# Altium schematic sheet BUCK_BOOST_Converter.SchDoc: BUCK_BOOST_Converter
size A3; Date: Not used; ApprovedBy: Not used; CheckedBy: Not used; Author: Not used; CompanyName: STMicroelectronics; DrawnBy: Not used; Engineer: Not used; Organization: Not used; Address1: Not used; Address2: Not used; Address3: Not used; Address4: Not used; DocumentNumber: Not used; Revision: Not used; SheetNumber: 7; SheetTotal: 12
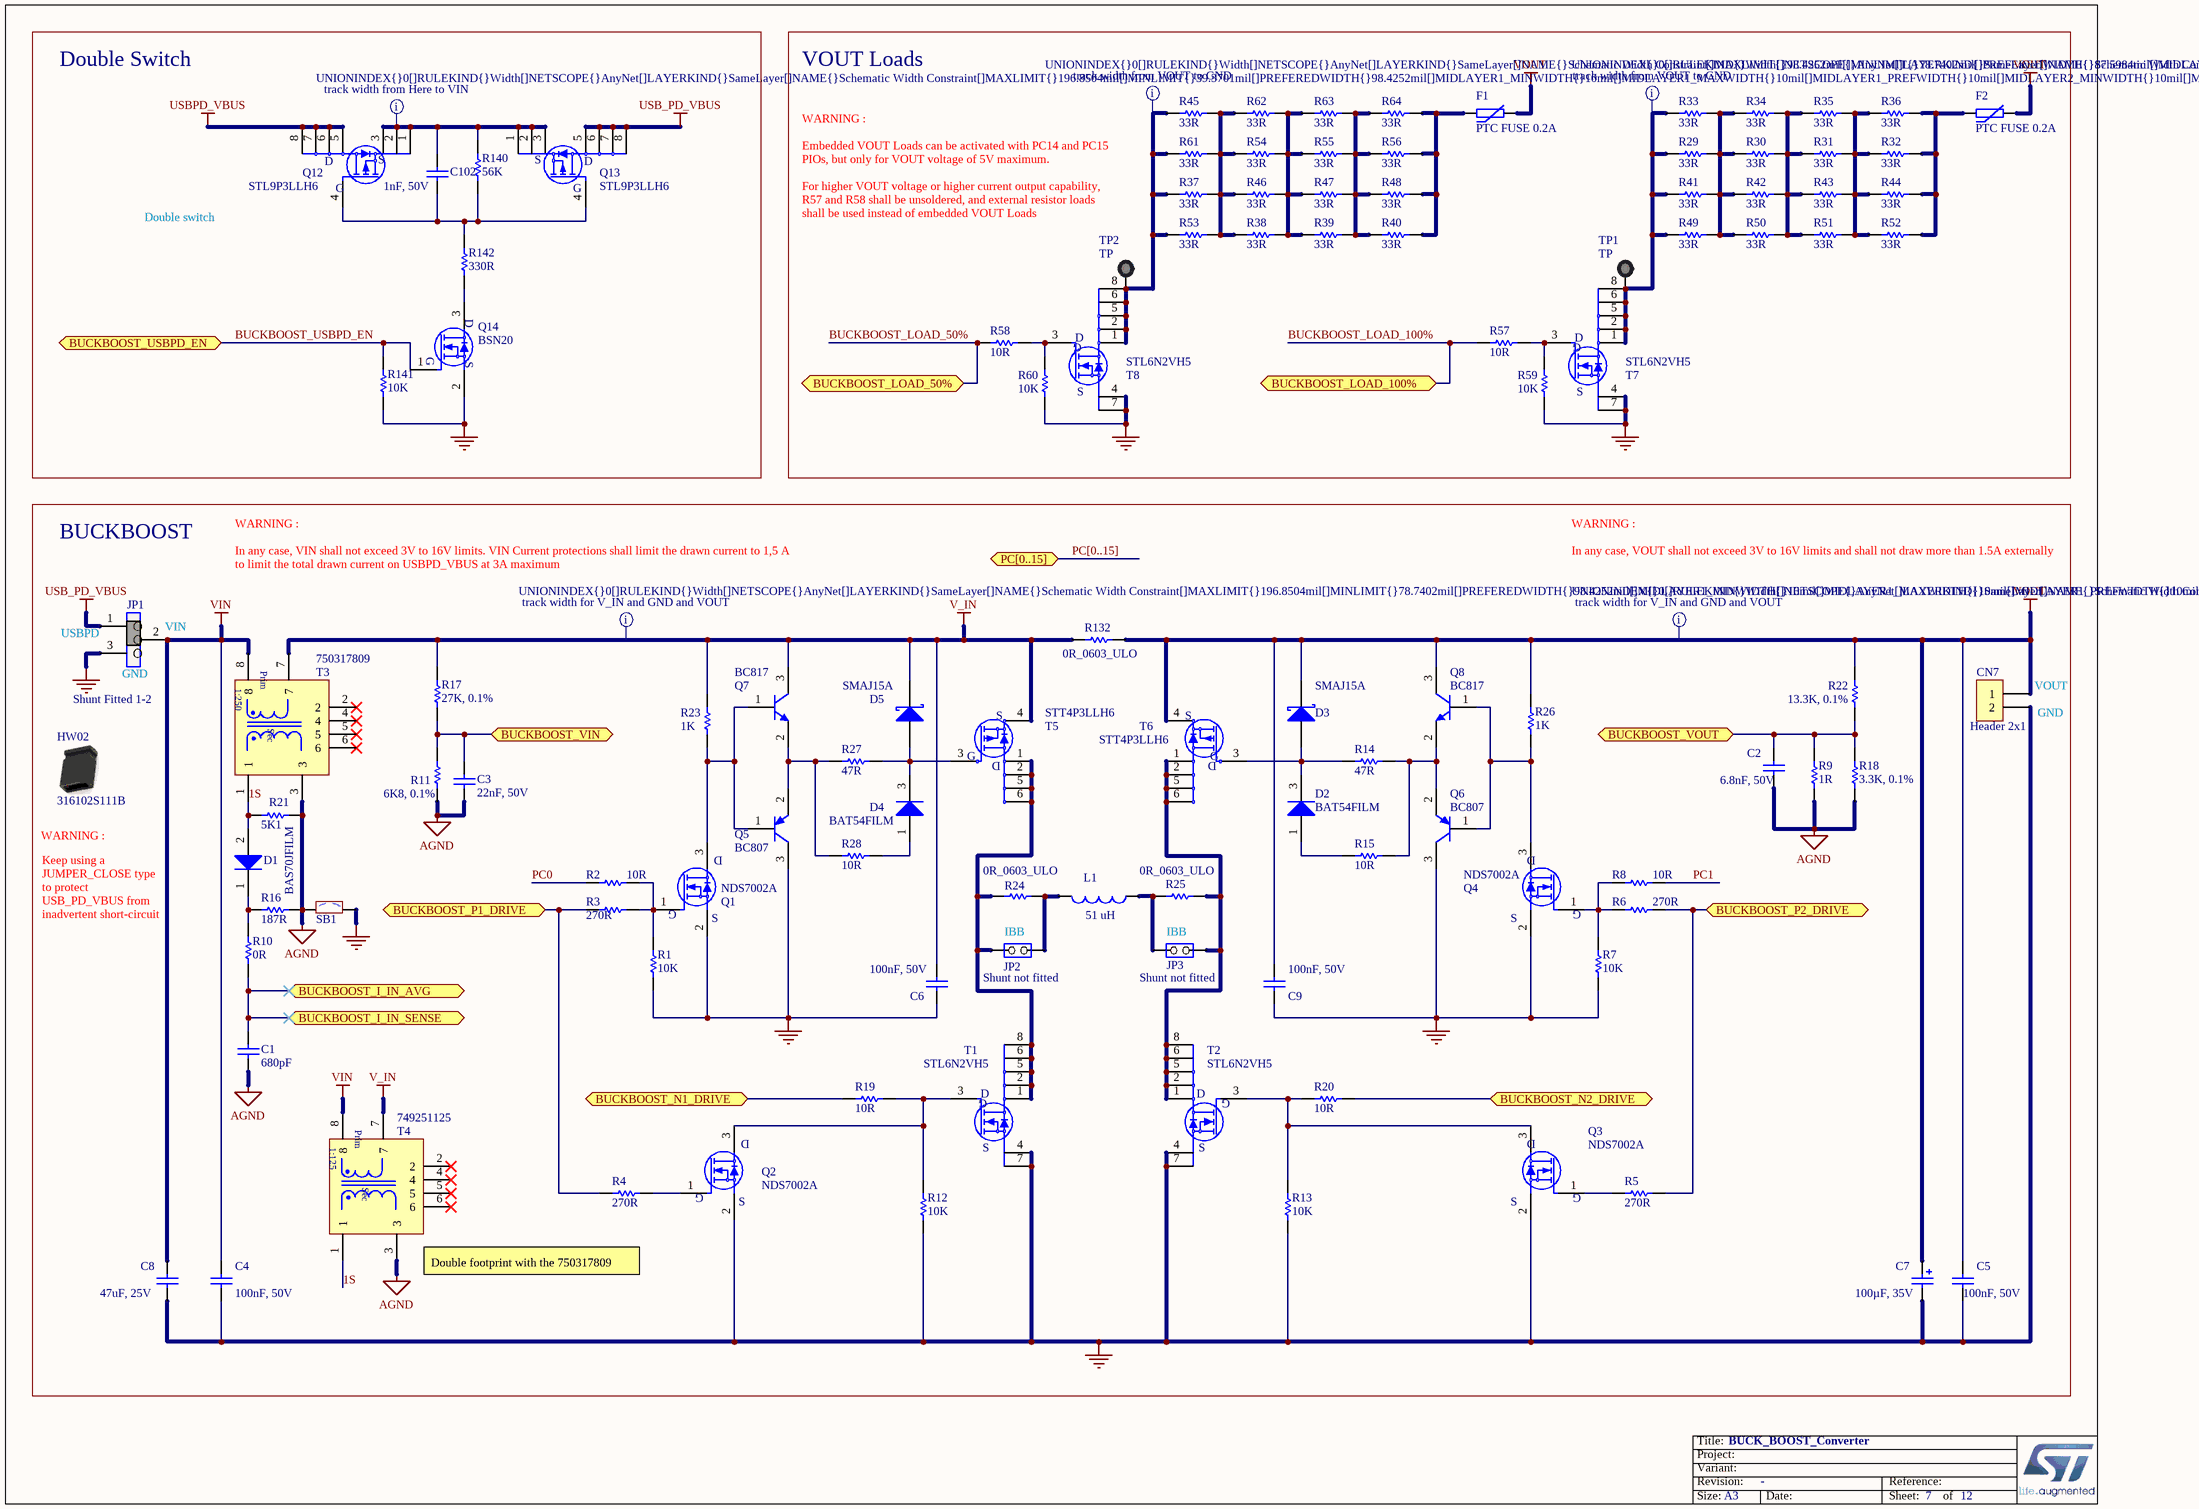
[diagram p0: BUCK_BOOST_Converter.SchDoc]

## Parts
C1  value 680pF  [C0603_H0P8]
C2  value 6.8nF, 50V  [C0603_H0P8]
C3  value 22nF, 50V  [C0603]
C4  value 100nF, 50V  [C0805_H0P85]
C5  value 100nF, 50V  [C0805_H0P85]
C6  value 100nF, 50V  [C0805_H0P85]
C7  value 100µF, 35V  [CPOL_WURTH_WCAP-ASLL_8X10P5]
C8  value 47uF, 25V  [C1206_H1P6]  (hidden comment: Capacitor)
C9  value 100nF, 50V  [C0805_H0P85]
C102  value 1nF, 50V  [C0805_H0P6]
CN7  Header 2x1  [CON_LYCONN_313102S141346]
D1  value BAS70JFILM  [DIO_SOD323_1K_2A]  (hidden comment: DIODE_1K_2A)
D2  value BAT54FILM  [DIO_SOT23_SC59_1A_2NC_3K_H1P4]
D3  value SMAJ15A  [DIO_SMA_1A_2K]
D4  value BAT54FILM  [DIO_SOT23_SC59_1A_2NC_3K_H1P4]
D5  value SMAJ15A  [DIO_SMA_1A_2K]
F1  value PTC FUSE 0.2A  [PTC_EATON_FUSE_PTS1812_H0P9]
F2  value PTC FUSE 0.2A  [PTC_EATON_FUSE_PTS1812_H0P9]
HW02  value 316102S111B  (hidden comment: JUMPER_CLOSE)
JP1  value Shunt Fitted 1-2  [CON_SAMTEC_TSW-103-07-F-S]  (hidden comment: Jumper_Header 3x1 Fitted 1-2)
JP2  value Shunt not fitted  [CON_988-JIUBABA_313102S111116]  (hidden comment: Jumper_Header 2x1)
JP3  value Shunt not fitted  [CON_988-JIUBABA_313102S111116]  (hidden comment: Jumper_Header 2x1)
L1  value 51 uH  [IND_SUNLORD_SWPA5040S]  (hidden comment: Inductor)
Q1  value NDS7002A  [ICC_SOT23-3L_H1P12]
Q2  value NDS7002A  [ICC_SOT23-3L_H1P12]
Q3  value NDS7002A  [ICC_SOT23-3L_H1P12]
Q4  value NDS7002A  [ICC_SOT23-3L_H1P12]
Q5  value BC807  [ICC_SOT23-3L_H1P12]
Q6  value BC807  [ICC_SOT23-3L_H1P12]
Q7  value BC817  [NPN_SOT23]
Q8  value BC817  [NPN_SOT23]
Q12  value STL9P3LLH6  [MOS_POWERFLAT_3P3X3P3_P065]
Q13  value STL9P3LLH6  [MOS_POWERFLAT_3P3X3P3_P065]
Q14  value BSN20  [MOS_SOT23]
R1  value 10K  [R0805]
R2  value 10R  [R0805_H0P5]
R3  value 270R  [R0805_H0P5]
R4  value 270R  [R0805_H0P5]
R5  value 270R  [R0805_H0P5]
R6  value 270R  [R0805_H0P5]
R7  value 10K  [R0805]
R8  value 10R  [R0805_H0P5]
R9  value 1R  [R1206_H0P55]
R10  value 0R  [R0603]  (hidden comment: Resistor)
R11  value 6K8, 0.1%  [R0805]
R12  value 10K  [R0805]
R13  value 10K  [R0805]
R14  value 47R  [R0805_H0P5]
R15  value 10R  [R0805_H0P5]
R16  value 187R  [R1206_H0P55]  (hidden comment: Resistor)
R17  value 27K, 0.1%  [R0805]
R18  value 3.3K, 0.1%  [R0805]
R19  value 10R  [R0805_H0P5]
R20  value 10R  [R0805_H0P5]
R21  value 5K1  [R0603]  (hidden comment: Resistor)
R22  value 13.3K, 0.1%  [R0805]
R23  value 1K  [R0603]
R24  value 0R_0603_ULO  [R0603]
R25  value 0R_0603_ULO  [R0603]
R26  value 1K  [R0603]
R27  value 47R  [R0805_H0P5]
R28  value 10R  [R0805_H0P5]
R29  value 33R  [R1206_H0P55]
R30  value 33R  [R1206_H0P55]
R31  value 33R  [R1206_H0P55]
R32  value 33R  [R1206_H0P55]
R33  value 33R  [R1206_H0P55]
R34  value 33R  [R1206_H0P55]
R35  value 33R  [R1206_H0P55]
R36  value 33R  [R1206_H0P55]
R37  value 33R  [R1206_H0P55]
R38  value 33R  [R1206_H0P55]
R39  value 33R  [R1206_H0P55]
R40  value 33R  [R1206_H0P55]
R41  value 33R  [R1206_H0P55]
R42  value 33R  [R1206_H0P55]
R43  value 33R  [R1206_H0P55]
R44  value 33R  [R1206_H0P55]
R45  value 33R  [R1206_H0P55]
R46  value 33R  [R1206_H0P55]
R47  value 33R  [R1206_H0P55]
R48  value 33R  [R1206_H0P55]
R49  value 33R  [R1206_H0P55]
R50  value 33R  [R1206_H0P55]
R51  value 33R  [R1206_H0P55]
R52  value 33R  [R1206_H0P55]
R53  value 33R  [R1206_H0P55]
R54  value 33R  [R1206_H0P55]
R55  value 33R  [R1206_H0P55]
R56  value 33R  [R1206_H0P55]
R57  value 10R  [R0805_H0P5]
R58  value 10R  [R0805_H0P5]
R59  value 10K  [R0603]
R60  value 10K  [R0603]
R61  value 33R  [R1206_H0P55]
R62  value 33R  [R1206_H0P55]
R63  value 33R  [R1206_H0P55]
R64  value 33R  [R1206_H0P55]
R132  value 0R_0603_ULO  [R0603]
R140  value 56K  [R0603]
R141  value 10K  [R0603]
R142  value 330R  [R0603]
SB1  (no value)  [SOLDER-BRIDGE_R0603-0R]
T1  value STL6N2VH5  [MOS_POWERFLAT_2X2_P065]
T2  value STL6N2VH5  [MOS_POWERFLAT_2X2_P065]
T3  value 750317809  [TRS_WURTH_750317809]
T4  value 749251125  [TRS_WURTH_749251125]
T5  value STT4P3LLH6  [MOS_SOT23-6L]
T6  value STT4P3LLH6  [MOS_SOT23-6L]
T7  value STL6N2VH5  [MOS_POWERFLAT_2X2_P065]
T8  value STL6N2VH5  [MOS_POWERFLAT_2X2_P065]
TP1  value TP  [TP_PTH_1MM_2MM]
TP2  value TP  [TP_PTH_1MM_2MM]

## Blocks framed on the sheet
Double Switch: C102 Q12-Q14 R140-R142
VOUT Loads: F1 F2 R29-R64 T7 T8 TP1 TP2
BUCKBOOST: C1-C9 CN7 D1-D5 HW02 JP1-JP3 L1 Q1-Q8 R1-R28 R132 SB1 T1-T6

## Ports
BUCKBOOST_I_IN_AVG, BUCKBOOST_I_IN_SENSE, BUCKBOOST_LOAD_50%, BUCKBOOST_LOAD_100%, BUCKBOOST_N1_DRIVE, BUCKBOOST_N2_DRIVE, BUCKBOOST_P1_DRIVE, BUCKBOOST_P2_DRIVE, BUCKBOOST_USBPD_EN, BUCKBOOST_VIN, BUCKBOOST_VOUT, PC[0..15] (bidir)

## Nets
AGND: C1.1 C2.1 C3.1 R9.1 R11.1 R16.2 R18.1 R21.2 SB1.1 T3.3 T4.3
GND: C4.1 C5.1 C6.1 C7.2 C8.1 C9.1 CN7.2 JP1.3 Q1.2(S) Q2.2(S) Q3.2(S) Q4.2(S) Q5.3(C) Q6.3(C) Q14.2(S) R1.1 R7.1 R12.1 R13.1 R59.1 R60.1 R141.1 SB1.2 T1.4(S) T1.7(S) T2.4(S) T2.7(S) T7.4(S) T7.7(S) T8.4(S) T8.7(S)
USB_PD_VBUS: JP1.1 Q13.5(D) Q13.6(D) Q13.7(D) Q13.8(D)
USBPD_VBUS: Q12.5(D) Q12.6(D) Q12.7(D) Q12.8(D)
V_IN: C6.2 D5.2(K) Q7.3(C) R17.2 R23.2 R132.1 T3.7 T4.7 T5.4(S)
VIN: C4.2 C8.2 JP1.2 T3.8 T4.8
VOUT: C5.2 C7.1 C9.2 CN7.1 D3.2(K) F1.2 F2.2 Q8.3(C) R22.2 R26.2 R132.2 T6.4(S)
1S: D1.2(A) R21.1 T3.1 T4.1
BUCKBOOST_I_IN_AVG: C1.2 R10.1 ; port BUCKBOOST_I_IN_AVG, port BUCKBOOST_I_IN_SENSE
BUCKBOOST_LOAD_50%: R58.1 ; port BUCKBOOST_LOAD_50%
BUCKBOOST_LOAD_100%: R57.1 ; port BUCKBOOST_LOAD_100%
BUCKBOOST_N1_DRIVE: R19.1 ; port BUCKBOOST_N1_DRIVE
BUCKBOOST_N2_DRIVE: R20.2 ; port BUCKBOOST_N2_DRIVE
BUCKBOOST_P1_DRIVE: R3.1 R4.1 ; port BUCKBOOST_P1_DRIVE
BUCKBOOST_P2_DRIVE: R5.2 R6.2 ; port BUCKBOOST_P2_DRIVE
BUCKBOOST_USBPD_EN: Q14.1(G) R141.2 ; port BUCKBOOST_USBPD_EN
BUCKBOOST_VIN: C3.2 R11.2 R17.1 ; port BUCKBOOST_VIN
BUCKBOOST_VOUT: C2.2 R9.2 R18.2 R22.1 ; port BUCKBOOST_VOUT
PC0: R2.1
PC1: R8.2
NetC102_1: C102.1 Q12.4(G) Q13.4(G) R140.2 R142.2
NetC102_2: C102.2 Q12.1(S) Q12.2(S) Q12.3(S) Q13.1(S) Q13.2(S) Q13.3(S) R140.1
NetD1_1: D1.1(K) R10.2 R16.1
NetD2_1: D2.1(A) R15.1
NetD2_3: D2.3(K) D3.1(A) R14.1 T6.3(G)
NetD4_1: D4.1(A) R28.2
NetD4_3: D4.3(K) D5.1(A) R27.2 T5.3(G)
NetF1_1: F1.1 R40.2 R48.2 R56.2 R64.2
NetF2_1: F2.1 R32.2 R36.2 R44.2 R52.2
NetJP2_1: JP2.1(COMMON) R24.1 T1.1(D) T1.2(D) T1.5(D) T1.6(D) T1.8(D) T5.1(S) T5.2(S) T5.5(D) T5.6(D)
NetJP2_2: JP2.2(NO) L1.2 R24.2
NetJP3_1: JP3.1(COMMON) L1.1 R25.1
NetJP3_2: JP3.2(NO) R25.2 T2.1(D) T2.2(D) T2.5(D) T2.6(D) T2.8(D) T6.1(S) T6.2(S) T6.5(D) T6.6(D)
NetQ1_1: Q1.1(G) R1.2 R2.2 R3.2
NetQ1_3: Q1.3(D) Q5.1(B) Q7.1(B) R23.1
NetQ2_1: Q2.1(G) R4.2
NetQ2_3: Q2.3(D) R12.2 R19.2 T1.3(G)
NetQ3_1: Q3.1(G) R5.1
NetQ3_3: Q3.3(D) R13.2 R20.1 T2.3(G)
NetQ4_1: Q4.1(G) R6.1 R7.2 R8.1
NetQ4_3: Q4.3(D) Q6.1(B) Q8.1(B) R26.1
NetQ5_2: Q5.2(E) Q7.2(E) R27.1 R28.1
NetQ6_2: Q6.2(E) Q8.2(E) R14.2 R15.2
NetQ14_3: Q14.3(D) R142.1
NetR29_1: R29.1 R33.1 R41.1 R49.1 T7.1(D) T7.2(D) T7.5(D) T7.6(D) T7.8(D) TP1.1
NetR29_2: R29.2 R30.1 R33.2 R34.1 R41.2 R42.1 R49.2 R50.1
NetR30_2: R30.2 R31.1 R34.2 R35.1 R42.2 R43.1 R50.2 R51.1
NetR31_2: R31.2 R32.1 R35.2 R36.1 R43.2 R44.1 R51.2 R52.1
NetR37_1: R37.1 R45.1 R53.1 R61.1 T8.1(D) T8.2(D) T8.5(D) T8.6(D) T8.8(D) TP2.1
NetR37_2: R37.2 R38.1 R45.2 R46.1 R53.2 R54.1 R61.2 R62.1
NetR38_2: R38.2 R39.1 R46.2 R47.1 R54.2 R55.1 R62.2 R63.1
NetR39_2: R39.2 R40.1 R47.2 R48.1 R55.2 R56.1 R63.2 R64.1
NetR57_2: R57.2 R59.2 T7.3(G)
NetR58_2: R58.2 R60.2 T8.3(G)

Not connected (* = marked no-connect by the designer): T3 2* 4* 5* 6*; T4 2* 4* 5* 6*

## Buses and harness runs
bus PC[0..15] = port PC[0..15]

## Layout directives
rule Width Constraint [Pref Width = 2.5mm    Min Width = 1mm    Max Width = 5mm]: NetC102_2
rule Width Constraint [Pref Width = 2.225mm    Min Width = 2mm    Max Width = 2.5mm]: NetR29_1, NetR37_1
rule Width Constraint [Pref Width = 2.5mm    Min Width = 2mm    Max Width = 5mm]: V_IN, VOUT

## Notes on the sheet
- WARNING :
- Embedded VOUT Loads can be activated with PC14 and PC15
- PIOs, but only for VOUT voltage of 5V maximum.
- Double switch
- (near R37) For higher VOUT voltage or higher current output capability,
- (near R37) R57 and R58 shall be unsoldered, and external resistor loads
- shall be used instead of embedded VOUT Loads
- to limit the total drawn current on USBPD_VBUS at 3A maximum
- In any case, VIN shall not exceed 3V to 16V limits. VIN Current protections shall limit the drawn current to 1,5 A
- In any case, VOUT shall not exceed 3V to 16V limits and shall not draw more than 1.5A externally
- (near JP1) USBPD
- (near JP1) VIN
- (near JP1) GND
- (near CN7) VOUT
- (near CN7) GND
- Keep using a
- JUMPER_CLOSE type
- to protect
- USB_PD_VBUS from
- inadvertent short-circuit
- (near JP2) IBB
- (near JP3) IBB
- (near T4) Double footprint with the 750317809

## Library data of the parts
C1 = MCD-01576: Capacitor, MLCC, 680pF, 16V, X7R, 10%, 0603, T=0.8mm; Manufacturer_Part_Number: CC0603KRX7R7BB681; Manufacturer: YAGEO; Provided_By: SUBCO
C2 = MCD-01544: Capacitor, MLCC, 6.8nF, 50V, X7R, 10%, 0603, T=0.8mm; Manufacturer_Part_Number: CC0603KRX7R9BB682; Manufacturer: YAGEO; Provided_By: SUBCO
C3 = MCD-01103: Capacitor,22nF,50V,X7R,10%,0603; Manufacturer_Part_Number: CC0603KRX7R9BB223; Manufacturer: YAGEO; Provided_By: SUBCO
C4-C6 C9 = MCD-01525: Capacitor, MLCC, 100nF, 50V, X7R, 10%, 0805, T=0,85mm; Manufacturer_Part_Number: CC0805KRX7R9BB104; Manufacturer: YAGEO; Provided_By: SUBCO
C7 = MCD-01683: Capacitor, Electrolytic, 100µF, 35V, 20%, SMT, D=8mm, T=10.5mm; Manufacturer_Part_Number: 865060553006; Manufacturer: WURTH ELEKTRONIK; Provided_By: SUBCO
C8 = MCD-01517: Capacitor, MLCC, 47uF, 25V, X5R, 20%, 1206, T=1,6mm; Manufacturer_Part_Number: C3216X5R1E476M160AC; Manufacturer: TDK; ECCN_US: EAR99; ECCN_EU: NEC; Provided_By: SUBCO
C102 = MCD-01549: Capacitor, MLCC, 1nF, 50V, X7R,10%, 0805, T=0,6mm; Manufacturer_Part_Number: CC0805KRX7R9BB102; Manufacturer: YAGEO; Provided_By: SUBCO
CN7 = MCD-01855: Header 2x1, 2.54mm, VR, TH, height 5.84mm/7.50 mm, height total 15.84 mm; Part_Type: Connector; Manufacturer_Part_Number: 313102S1411584; Manufacturer: LYCONN; Provided_By: SUBCO
D1 = MCD-01880: ultrafast and RF switching diode, VF = 0.41 V @ IF = 1mA; VR = 70V;; Manufacturer: STMICROELECTRONICS; Provided_By: SUBCO with ST control
D2 D4 = MCD-01524: Single surface mount small signal schotky diode; Manufacturer: STMICROELECTRONICS; Provided_By: SUBCO with ST control
D3 D5 = MCD-01522: Transil unidirectional diode Vrm=15V, Vbr=16.7V(1mA), Vcl=32.5V(71A), SMA; Manufacturer_Part_Number: SMAJ15A-TR; Manufacturer: STMICROELECTRONICS; Provided_By: SUBCO with ST control
F1 F2 = MCD-01682: SMD, PTC resettable fuse, IH:0.2A, IT:0.4A, Vdc_max:30V, Rmax:5 ohm; Part_Type: Misc; Manufacturer_Part_Number: PTS181230V020; Manufacturer: EATON; Provided_By: SUBCO
HW02 = MCD-01864: Jumper, height 6.5 mm, Black, 2.54mm, 3A, 20 mohm, close; Part_Type: Mechanical; Manufacturer: JIUBABA; Provided_By: SUBCO
JP1 = MCD-00684: Header, 3x1, 2,54mm, VR, TH, Height 5.84mm/2.54mm - Shunt Fitted 1-2 by default; Part_Type: Connector; Manufacturer_Part_Number: TSW-103-07-F-S; Manufacturer: SAMTEC; Provided_By: SUBCO
JP2 JP3 = MCD-01660: Header 2x1, 2.54mm, VR, TH, height 6 mm / 3 mm, total 11.6mm - Shunt not Fitted by default; Part_Type: Connector; Manufacturer_Part_Number: 313102S111116; Manufacturer: JIUBABA; Provided_By: SUBCO
L1 = MCD-01787: SMD Wire wound power inductor, 51uH, 20%, Isat 1.2A, 380mohm, 5.0x5.0x4.0mm; Manufacturer_Part_Number: SWPA5040S510MT; Manufacturer: SUNLORD; Provided_By: SUBCO
Q1-Q4 = MCD-01518: MOSFET, Single N-Channel , Vgs(th): 2.5V, Id: 280mA, Vds(max): 60V, Vgs(max): +/-20V, Rdson:3 ohm@Vgs=5V; Part_Type: IC; Manufacturer: ON SEMICONDUCTOR; Alternate_Manufacturer: FAIRCHILD; Provided_By: SUBCO
Q5 Q6 = MCD-01527: Transistor Bipolar PNP, 45V, 500mA, 100MHz, 300mW, SOT23-3; Part_Type: IC; Manufacturer: NEXPERIA; Alternate_Manufacturer: NXP; Provided_By: SUBCO
Q7 Q8 = MCD-01526: Transistor Bipolar NPN, 45V, 500mA, 100MHz, 300mW, SOT23-3; Part_Type: IC; Manufacturer: NEXPERIA; Alternate_Manufacturer: NXP; Provided_By: SUBCO
Q12 Q13 = MCD-01126: Power Mosfet, P-channel,VDS -30V,RDS 12mohm typ,ID -9A; Part_Type: IC; Manufacturer: STMICROELECTRONICS; Provided_By: SUBCO with ST control
Q14 = MCD-00151: N-channel enhancement mode field-effect transistor; Part_Type: IC; Manufacturer: NXP; Provided_By: SUBCO
R1 R7 R12 R13 = MCD-01154: Resistor,10K,0805,1%,1/8W; Manufacturer_Part_Number: RC0805FR-0710KL; Manufacturer: YAGEO; Provided_By: SUBCO
R2 R8 R15 R19 R20 R28 R57 R58 = MCD-01548: Resistor,10R,0805,1%, 1/8W; Manufacturer_Part_Number: RC0805FR-0710RL; Manufacturer: YAGEO; Provided_By: SUBCO
R3-R6 = MCD-01537: Resistor,270R,0805,1%,1/8W; Manufacturer_Part_Number: RC0805FR-07270RL; Manufacturer: YAGEO; Provided_By: SUBCO
R9 = MCD-01546: Resistor, 1R, 1206, 0.1%, 1/4W; Manufacturer_Part_Number: RT1206BRD071RL; Manufacturer: YAGEO; Provided_By: SUBCO
R10 = MCD-00056: Resistor,0R,0603,5%,1/10W; Manufacturer_Part_Number: RC0603JR-070RL; Manufacturer: YAGEO; ECCN_US: EAR99; ECCN_EU: NEC; Provided_By: SUBCO
R11 = MCD-01654: Resistor, 6K8, 0805, 0.1%, 1/8W, 50ppm; Manufacturer_Part_Number: AR05BTD6801; Manufacturer: VIKING; Provided_By: SUBCO
R14 R27 = MCD-01547: Resistor,47R,0805,1%,1/8W; Manufacturer_Part_Number: RC0805FR-0747RL; Manufacturer: YAGEO; Provided_By: SUBCO
R16 = MCD-01881: Resistor,187R,1206,1%,1/4W; Manufacturer_Part_Number: RC1206FR-07187RL; Manufacturer: YAGEO; Provided_By: SUBCO
R17 = MCD-01652: Resistor, 27K, 0805, 0.1%, 1/8W, 50ppm; Manufacturer_Part_Number: AR05BTD2702; Manufacturer: VIKING; Provided_By: SUBCO
R18 = MCD-01653: Resistor, 3K3, 0805, 0.1%, 1/8W, 50ppm; Manufacturer_Part_Number: AR05BTD3301; Manufacturer: VIKING; Provided_By: SUBCO
R21 = MCD-01882: Resistor,5K1,0603,1%,1/10W; Manufacturer_Part_Number: RC0603FR-075K1L; Manufacturer: YAGEO; Provided_By: SUBCO
R22 = MCD-01649: Resistor, 13K3, 0805, 0.1%, 1/8W, 50ppm; Manufacturer_Part_Number: AR05BTD1332; Manufacturer: VIKING; Provided_By: SUBCO
R23 R26 = MCD-00070: Resistor,1K,0603,1%,1/10W; Manufacturer_Part_Number: RC0603FR-071KL; Manufacturer: YAGEO; Provided_By: SUBCO
R24 R25 R132 = MCD-00181: Resistor,0R,0603,ULO; Manufacturer_Part_Number: PMR03EZPJ000; Manufacturer: ROHM; Provided_By: SUBCO
R29-R56 R61-R64 = MCD-01681: Resistor,33R,1206,1%,1/4W; Manufacturer_Part_Number: RC1206FR-0733RL; Manufacturer: YAGEO; Provided_By: SUBCO
R59 R60 R141 = MCD-00220: Resistor,10K,0603,1%,1/10W; Manufacturer_Part_Number: RC0603FR-0710KL; Manufacturer: YAGEO; Provided_By: SUBCO
R140 = MCD-00494: Resistor,56K,0603,1%,1/10W; Manufacturer_Part_Number: RC0603FR-0756KL; Manufacturer: YAGEO; Provided_By: SUBCO
R142 = MCD-00197: Resistor,330R,0603,1%,1/10W; Manufacturer_Part_Number: RC0603FR-07330RL; Manufacturer: YAGEO; BMS_Part_Number: 9129729; Provided_By: SUBCO
SB1 = MCD-00072: Solder Bridge OFF; Part_Type: Mechanical; Manufacturer_Part_Number: RC0603JR-070RL; Manufacturer: YAGEO; Provided_By: SUBCO
T1 T2 T7 T8 = MCD-01028: N-channel 20 V, 0.025 O typ., 6 A STripFET™ V Power MOSFET in a PowerFLAT™ 2x2 package; Part_Type: IC; Manufacturer: STMICROELECTRONICS; BMS_Part_Number: 9153558; Provided_By: SUBCO with ST control
T3 = MCD-01596: Current Sense Transformer, 1:250 ratio, xx mohm / 20 ohms, 11mH, 10A; Part_Type: Inductor; Manufacturer: WURTH ELEKTRONIK; Provided_By: SUBCO
T4 = MCD-01570: Current Sense Transformer, 1:125 ratio, 6 mohm / 6.5 ohms, 3mH, 10A; Part_Type: IC; Manufacturer: WURTH ELEKTRONIK; Provided_By: SUBCO
T5 T6 = MCD-00574: Power MOSFET - P-Channel 30 V, 0.048 ? typ., 4 A STripFET H6 DeepGATE - SOT23-6L; Part_Type: IC; Manufacturer: STMICROELECTRONICS; Alternate_Manufacturer_Part_Number: STT7P2UH7; BMS_Part_Number: 9153046; Provided_By: SUBCO with ST control
TP1 TP2 = MCD-01506: Test Point trought hole 1mm/2mm; Part_Type: Mechanical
